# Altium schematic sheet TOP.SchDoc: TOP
size A4; CompanyName: Arduino srl; DrawnBy: Silvio Navaretti; DocumentNumber: ASX00039; SheetNumber: 1; SheetTotal: 8; RevAuthor: Silvio Navaretti
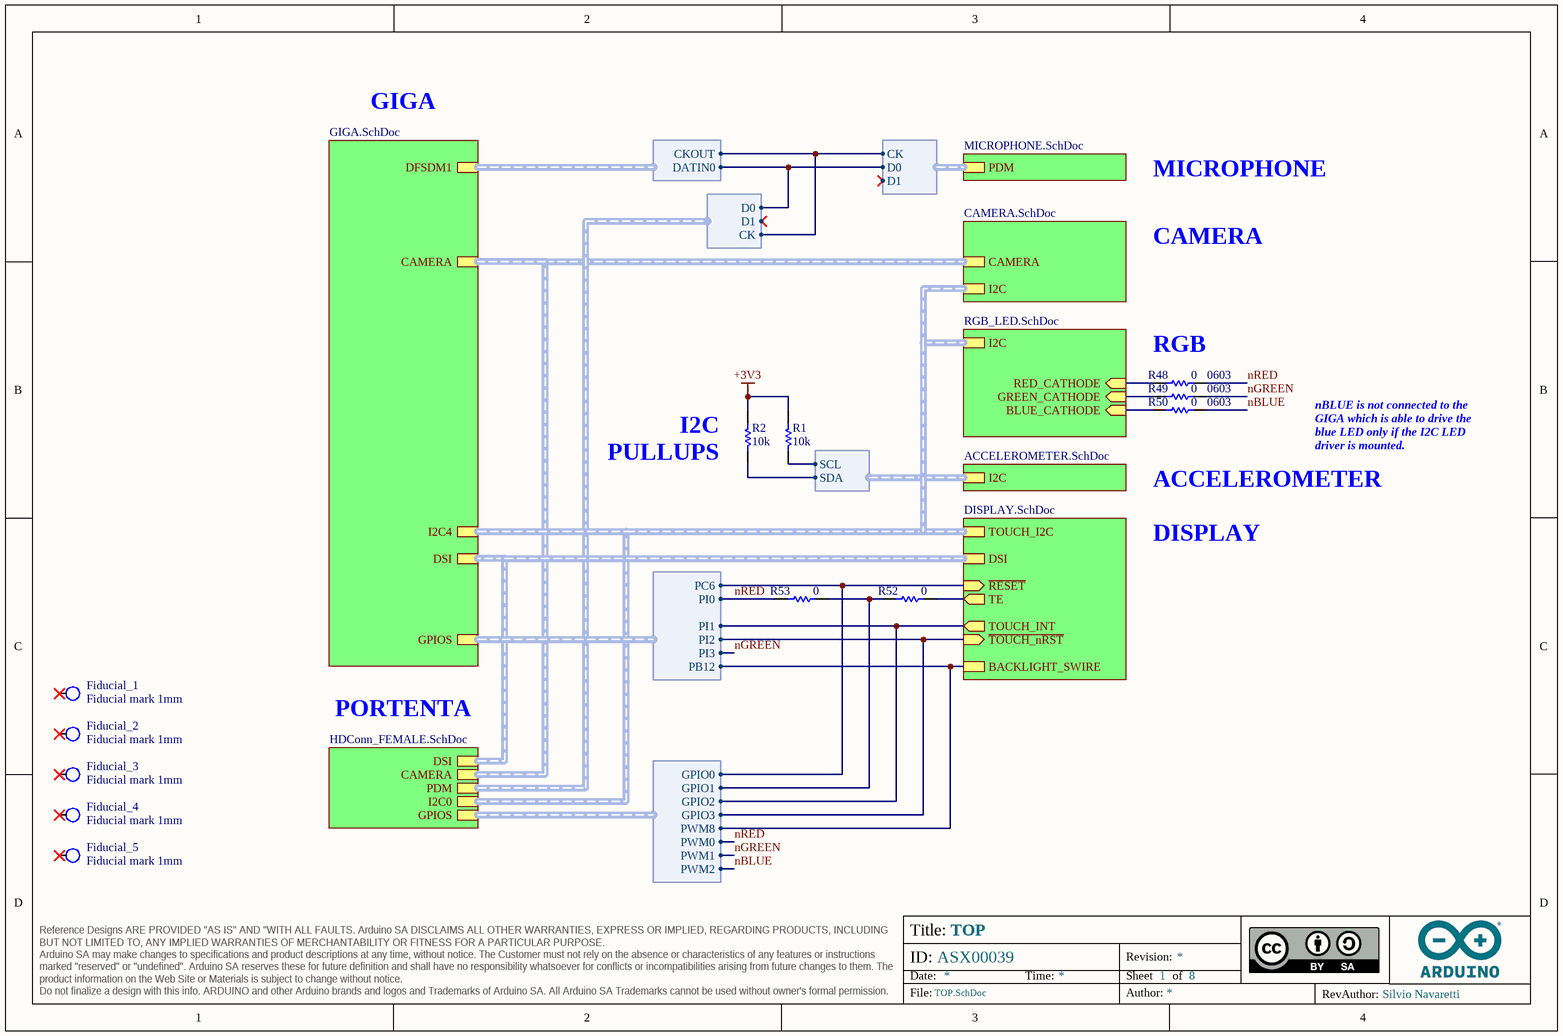
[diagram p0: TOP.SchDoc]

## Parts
Fiducial_1  Fiducial mark 1mm  [Fiducial mark 1mm-Footprint-1]  (no BOM)
Fiducial_2  Fiducial mark 1mm  [Fiducial mark 1mm-Footprint-1]  (no BOM)
Fiducial_3  Fiducial mark 1mm  [Fiducial mark 1mm-Footprint-1]  (no BOM)
Fiducial_4  Fiducial mark 1mm  [Fiducial mark 1mm-Footprint-1]  (no BOM)
Fiducial_5  Fiducial mark 1mm  [Fiducial mark 1mm-Footprint-1]  (no BOM)
R1  value 10k  [RES-0603]  (hidden comment: CRCW060310K0JNEAC)
R2  value 10k  [RES-0603]  (hidden comment: CRCW060310K0JNEAC)
R48  value 0  Case Code (Imperial): 0603  [RES-0603]  (hidden comment: CRCW06030000Z0EAC)
R49  value 0  Case Code (Imperial): 0603  [RES-0603]  (hidden comment: CRCW06030000Z0EAC)
R50  value 0  Case Code (Imperial): 0603  [RES-0603]  (hidden comment: CRCW06030000Z0EAC)
R52  value 0  [RES-0603]  (hidden comment: CRCW06030000Z0EAC)
R53  value 0  [RES-0603]  (hidden comment: CRCW06030000Z0EAC)

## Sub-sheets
ACCELEROMETER = ACCELEROMETER.SchDoc: I2C (harness I2C)
CAMERA = CAMERA.SchDoc: I2C (harness I2C), CAMERA (harness PDM)
DISPLAY = DISPLAY.SchDoc: DSI (harness DISPLAY), TE (out), ~{RESET} (in), BACKLIGHT_SWIRE, TOUCH_I2C (harness I2C), TOUCH_INT (out), ~{TOUCH_nRST} (in)
GIGA_HEADERS = GIGA.SchDoc: CAMERA (harness PDM), DSI (harness DISPLAY), GPIOS (harness GIGA_GPIOS), DFSDM1 (harness DFSDM), I2C4 (harness I2C)
PORTENTA = HDConn_FEMALE.SchDoc: CAMERA (harness PDM), DSI (harness DISPLAY), GPIOS (harness PORTENTA_GPIO), I2C0 (harness I2C), PDM (harness PDM)
U_MICROPHONE = MICROPHONE.SchDoc: PDM (harness PDM)
U_RGB_LED = RGB_LED.SchDoc: I2C (harness I2C), RED_CATHODE (in), GREEN_CATHODE (in), BLUE_CATHODE (in)

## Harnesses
I2C: SDA, SCL
DFSDM: DATIN0, CKOUT
PDM: CK, D0, D1
GIGA_GPIOS: PC6, PI0, PI1, PI2, PI3, PB12
PORTENTA_GPIO: GPIO0, GPIO1, GPIO2, GPIO3, PWM8, PWM0, PWM1, PWM2

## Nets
+3V3: R1.2 R2.2
nBLUE: R50.2 ; sheet PORTENTA/GPIOS.PWM2
nGREEN: R49.2 ; sheet GIGA_HEADERS/GPIOS.PI3, sheet PORTENTA/GPIOS.PWM1
nRED: R48.2 R53.1 ; sheet GIGA_HEADERS/GPIOS.PI0, sheet PORTENTA/GPIOS.PWM0
NetR1_1: R1.1 ; sheet DISPLAY/TOUCH_I2C.SCL
NetR2_1: R2.1 ; sheet DISPLAY/TOUCH_I2C.SDA
NetR48_1: R48.1 ; sheet U_RGB_LED/RED_CATHODE
NetR49_1: R49.1 ; sheet U_RGB_LED/GREEN_CATHODE
NetR50_1: R50.1 ; sheet U_RGB_LED/BLUE_CATHODE
NetR52_1: R52.1 R53.2 ; sheet PORTENTA/GPIOS.GPIO1
NetR52_2: R52.2 ; sheet DISPLAY/TE
(unnamed): sheet DISPLAY/~{RESET}, sheet GIGA_HEADERS/GPIOS.PC6, sheet PORTENTA/GPIOS.GPIO0
(unnamed): sheet DISPLAY/BACKLIGHT_SWIRE, sheet GIGA_HEADERS/GPIOS.PB12, sheet PORTENTA/GPIOS.PWM8  [a separate net that carries the same name]
(unnamed): sheet DISPLAY/TOUCH_INT, sheet GIGA_HEADERS/GPIOS.PI1, sheet PORTENTA/GPIOS.GPIO2  [a separate net that carries the same name]
(unnamed): sheet DISPLAY/~{TOUCH_nRST}, sheet GIGA_HEADERS/GPIOS.PI2, sheet PORTENTA/GPIOS.GPIO3  [a separate net that carries the same name]
(unnamed): sheet GIGA_HEADERS/DFSDM1.DATIN0, sheet PORTENTA/PDM.D0, sheet U_MICROPHONE/PDM.D0  [a separate net that carries the same name]
(unnamed): sheet GIGA_HEADERS/DFSDM1.CKOUT, sheet PORTENTA/PDM.CK, sheet U_MICROPHONE/PDM.CK  [a separate net that carries the same name]

Not connected (* = marked no-connect by the designer): Fiducial_1 1*; Fiducial_2 1*; Fiducial_3 1*; Fiducial_4 1*; Fiducial_5 1*

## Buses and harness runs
harness sheet ACCELEROMETER/I2C = sheet CAMERA/I2C = sheet DISPLAY/TOUCH_I2C = sheet GIGA_HEADERS/I2C4 = sheet PORTENTA/I2C0 = sheet U_RGB_LED/I2C
harness sheet CAMERA/CAMERA = sheet GIGA_HEADERS/CAMERA = sheet PORTENTA/CAMERA
harness sheet DISPLAY/DSI = sheet GIGA_HEADERS/DSI = sheet PORTENTA/DSI

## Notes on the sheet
- GIGA
- MICROPHONE
- CAMERA
- RGB
- nBLUE is not connected to the GIGA which is able to drive the blue LED only if the I2C LED driver is mounted.
- (near R2) I2C
  PULLUPS
- ACCELEROMETER
- DISPLAY
- PORTENTA

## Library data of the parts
Fiducial_1-Fiducial_5 = UT0023-A.6: Fiducial mark 1mm clearance 2mm
R1 R2 = R0090-A.13: RES CHIP 0603 10k 5% 1/10W B.5k; Manufacturer: Vishay; Code Arduino: 0028; Power: 100mW
R48-R50 R52 R53 = R0096-A.13: RES CHIP 0603 0R 1/10W; Manufacturer: Vishay; Power: 100mW; Tolerance: J; Code Arduino: 0233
